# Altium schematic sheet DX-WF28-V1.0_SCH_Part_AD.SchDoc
size 1117 x 863 mm; SchematicName: $$$NONE
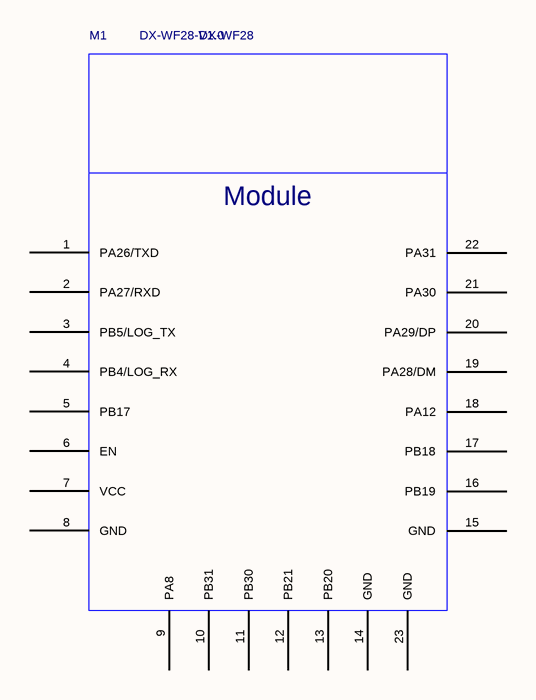
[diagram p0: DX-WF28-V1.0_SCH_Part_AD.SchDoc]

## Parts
M1  DX-WF28  value DX-WF28-V1.0  [DX-WF28]

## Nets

Not connected (* = marked no-connect by the designer): M1 1(PA26/TXD) 2(PA27/RXD) 3(PB5/LOG_TX) 4(PB4/LOG_RX) 5(PB17) 6(EN) 7(VCC) 8(GND) 9(PA8) 10(PB31) 11(PB30) 12(PB21) 13(PB20) 14(GND) 15(GND) 16(PB19) 17(PB18) 18(PA12) 19(PA28/DM) 20(PA29/DP) 21(PA30) 22(PA31) 23(GND)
